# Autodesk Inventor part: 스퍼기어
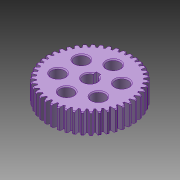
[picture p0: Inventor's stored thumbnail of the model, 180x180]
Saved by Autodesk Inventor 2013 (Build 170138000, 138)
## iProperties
Created: 2010-04
Part Number: 스퍼기어
Material: 강철, 탄소
Document SubType Name: Modeling
Designer: 진현석
Categories: <?xml version="1.0" encoding="UTF-16"?> <MemberInstance><Categories><FamilyTemplate><FamilyTemplateParameter ValueType="xs:double" Id="1" ObjectReferenceKey="da
Density: 1 g/cm^3
CustomPartVersion: 1
Author: 진현석
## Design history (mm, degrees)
sketch "Sketch1"
  geometry: C1 r 45 at (0, 0)
  constraints: 1 centre point
  dimensions: "d0" = 90 diameter of C1 (= da_da)
extrude "Extrusion1" new body sketch "Sketch1" distance "d1" = 22 (= da_b); taper "d2" = 0 deg
workplane "Work Plane2"
feature "피치 지름" dims "d4" = 10, "d5" = 0
workplane "Work Plane8"
workplane "Work Plane9"
feature "스퍼 기어" dims "da_b" = 22, "da_d" = 86, "da_aw" = 129, "da_da" = 90, "da_df" = 81, "da_dw" = 86, angle "da_beta" = 0 deg, "da_lefttooth" = 0, "da_righttooth" = 0
chamfer "모따기1" distance "d49" = 1; stored, may be unused: second distance "d50" = 2, angle "d51" = 45 deg
sketch "스케치3"
  geometry: L1 (-2.5, 9.3)-(2.5, 9.3); L2 (2.5, 9.3)-(2.5, 3.359); L3 (2.5, 3.359)-(-2.5, 3.359); L4 (-2.5, 3.359)-(-2.5, 9.3); C1 r 7 at (0, 0); A1 r 44 centre (0, 0) between (40.958, 16.077) and (40.001, 18.327) reference; A2 r 40.5 centre (0, 0) between (38.563, 12.374) and (38.086, 13.775) reference; 1 further point
  constraints: 8 end point, 2 parallel, 1 centre point, 1 coincident, 1 horizontal, 1 midpoint, 1 perpendicular, 1 vertical alignment
  dimensions: "d52" = 14 diameter of C1; "d53" = 2.3 distance edge to line of C1 L1; "d54" = 5 distance of L1.start L1.end
extrude "돌출2" cut sketch "스케치3" stored distance "d55" = 10; taper "d56" = 0 deg
sketch "스케치4"
  geometry: C1 r 7 at (0, 25); A1 r 7 centre (0, 0) between (-2.5, 6.538) and (2.5, 6.538) reference; A2 r 40.5 centre (0, 0) between (36.351, 17.857) and (35.674, 19.173) reference
  constraints: 1 centre point, 1 vertical alignment
  dimensions: "d57" = 25 distance of A1.centre C1.centre; "d58" = 14 diameter of C1
extrude "돌출3" cut sketch "스케치4" stored distance "d59" = 10; taper "d60" = 0 deg
chamfer "모따기2" distance "d65" = 1; stored, may be unused: second distance "d66" = 2, angle "d67" = 45 deg
body "Solid1"
pattern_circular "원형 패턴1" dims angle "d63" = 360 deg
sketch "Sketch2"
  geometry: C1 r 45 at (0, 0) reference; C2 r 43 at (0, 0)
  constraints: 1 centre point, 1 coincident
  dimensions: "d3" = 86 diameter of C2 (= da_dw)
body "Srf1"
other parameters: "d16" = 129 (= da_aw), "d17" = 0, "d34" = 0.7306 (computed from da_z), "d39" = 0, "d41" = 0, "d43" = 129 (= da_aw), "d46" = 129 (= da_aw), "d47" = 0, "d48" = 0
